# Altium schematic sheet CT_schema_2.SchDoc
size 276 x 169 mm
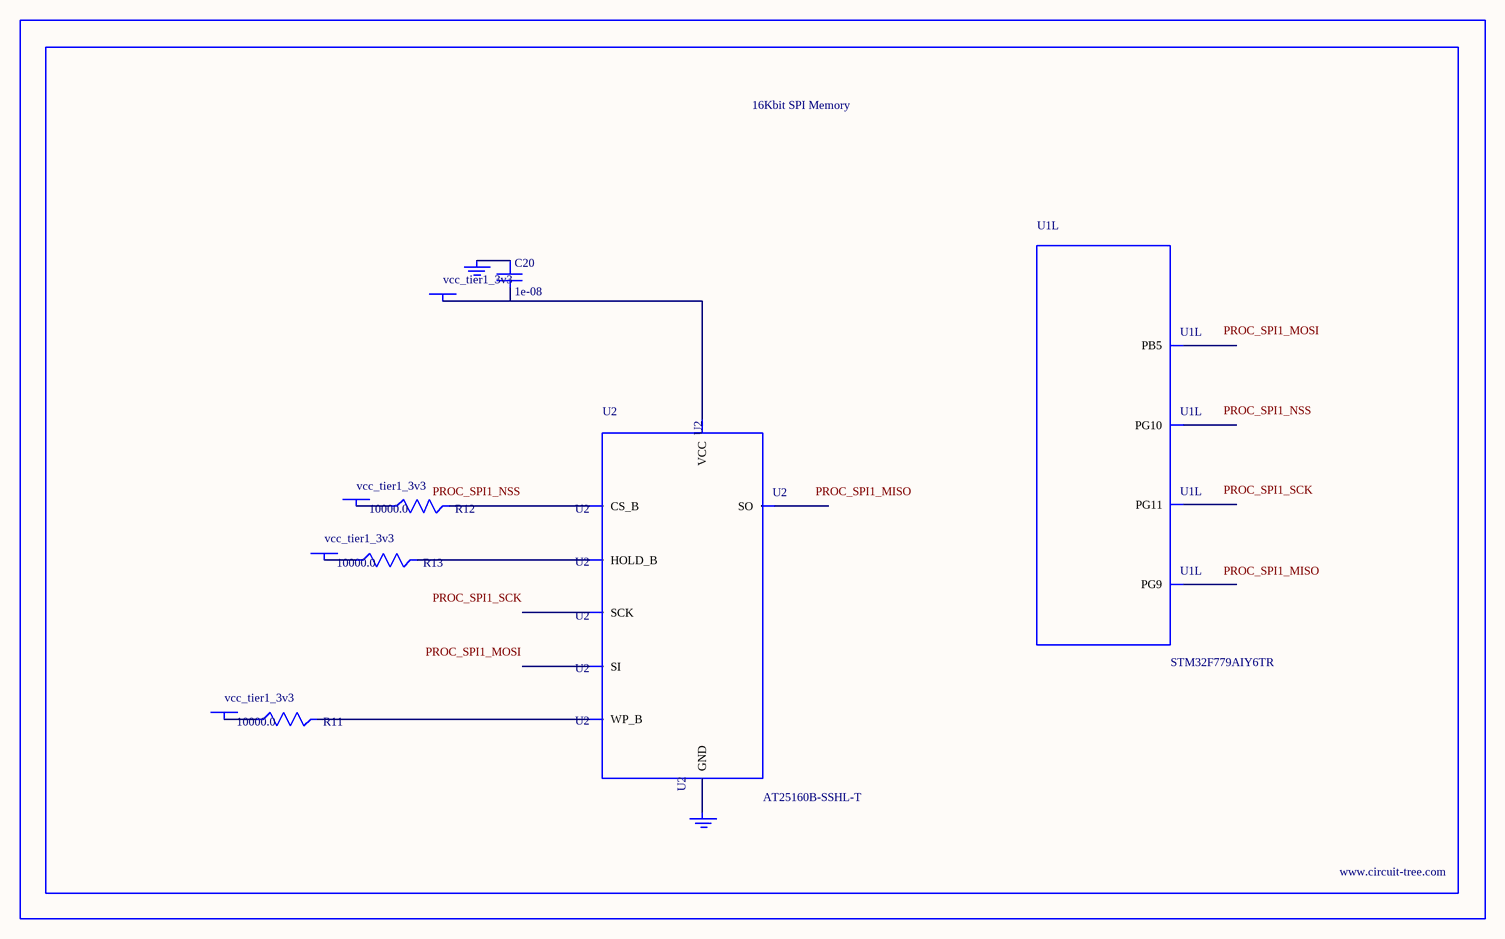
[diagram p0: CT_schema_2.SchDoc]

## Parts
BORDER1  (no value)
C20  1e-08  [C0402]
GND_INSTANCE_1_0  (no value)
GND_INSTANCE_1_1  (no value)
POWER_INSTANCE_1_0  vcc_tier1_3v3
POWER_INSTANCE_1_1  vcc_tier1_3v3
POWER_INSTANCE_1_2  vcc_tier1_3v3
POWER_INSTANCE_1_3  vcc_tier1_3v3
R11  10000.0  [R0603]
R12  10000.0  [R0603]
R13  10000.0  [R0603]
U1  STM32F779AIY6TR  [WLCSP180]  (part L of 15)
U2  AT25160B-SSHL-T  [SOIC-8]

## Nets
NetC20_1: C20.1 GND_INSTANCE_1_0.0(GND)
NetC20_2: C20.2 POWER_INSTANCE_1_3.0(PWR) U2.8(VCC)
NetGND_INSTANCE_1_1_0: GND_INSTANCE_1_1.0(GND) U2.4(GND)
NetPOWER_INSTANCE_1_0_0: POWER_INSTANCE_1_0.0(PWR) R12.1
NetPOWER_INSTANCE_1_1_0: POWER_INSTANCE_1_1.0(PWR) R11.1
NetPOWER_INSTANCE_1_2_0: POWER_INSTANCE_1_2.0(PWR) R13.1
NetR11_2: R11.2 U2.3(WP_B)
NetR12_2: R12.2 U2.1(CS_B)
NetR13_2: R13.2 U2.7(HOLD_B)

Not connected (* = marked no-connect by the designer): U1 A7(PG10) A9(PB5) B7(PG11) C6(PG9); U2 2(SO) 5(SI) 6(SCK)

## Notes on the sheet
- Labels drawn without touching a wire or pin: PROC_SPI1_MISO, PROC_SPI1_MOSI, PROC_SPI1_NSS, PROC_SPI1_SCK

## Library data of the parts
BORDER1 = BORDER_PAGE1
C20 = C0402C103K3RAC
GND_INSTANCE_1_0 GND_INSTANCE_1_1 = GND
POWER_INSTANCE_1_0-POWER_INSTANCE_1_3 = PWR
R11-R13 = RC0603JR-0710KL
